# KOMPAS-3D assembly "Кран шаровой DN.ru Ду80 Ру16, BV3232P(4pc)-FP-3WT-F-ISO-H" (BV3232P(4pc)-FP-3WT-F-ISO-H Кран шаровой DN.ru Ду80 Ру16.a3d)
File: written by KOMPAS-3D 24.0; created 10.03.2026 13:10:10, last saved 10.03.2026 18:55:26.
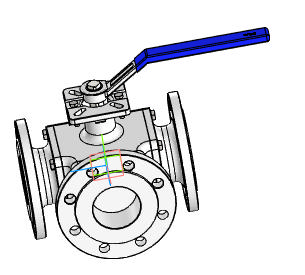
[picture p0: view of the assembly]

Document properties: Автор: R2D2; Полное имя файла: E:\Работа\Зайцев\BV3232P(4pc)-FP-3WT-F-ISO-H Кран шаровой DN.ru Ду15-100 Ру16\DN80\исходные материалы\BV3232P(4pc)-FP-3WT-F-ISO-H Кран шаровой DN.ru Ду80 Ру16.a3d

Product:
- Component [assembly]: Сборка1  | qty 1  | pos. 1  | Масса: 39.431387; Автор: R2D2; source file: dn80_3d_step.a3d
- Part/product: Кран шаровой DN.ru Ду80 Ру16  | designation BV3232P(4pc)-FP-3WT-F-ISO-H
    Масса: 39.1
    Раздел спецификации: Прочие изделия
    Примечание: D160-36353

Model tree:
1. Эскиз:1  (labels: Грань.Твердое тело1; Ребро.Твердое тело1)
2. Элемент выдавливания:1  (labels: Грань.Твердое тело1; Твердое тело1)
     Расстояние 2 = 0.01

Referenced files in E:\Работа\Зайцев\BV3232P(4pc)-FP-3WT-F-ISO-H Кран шаровой DN.ru Ду15-100 Ру16\DN80\исходные материалы\: dn80_3d_step.a3d
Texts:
  BV3232P(4pc)-FP-3WT-F-ISO-H
  Сборка1 Сборка1
  Ось Z.Начало координат
  Ось Y.Начало координат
